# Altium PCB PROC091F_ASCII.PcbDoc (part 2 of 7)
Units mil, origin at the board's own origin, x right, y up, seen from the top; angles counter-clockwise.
Board outline 3590.95 x 906.17 mil, 8 copper layers (Top Layer, GND1, Sig1, PWR1, PWR2, Sig2, GND2, Bottom Layer), stack 63.146 mil thick; 420 components, 316 nets, 1432 pads, 774 vias.
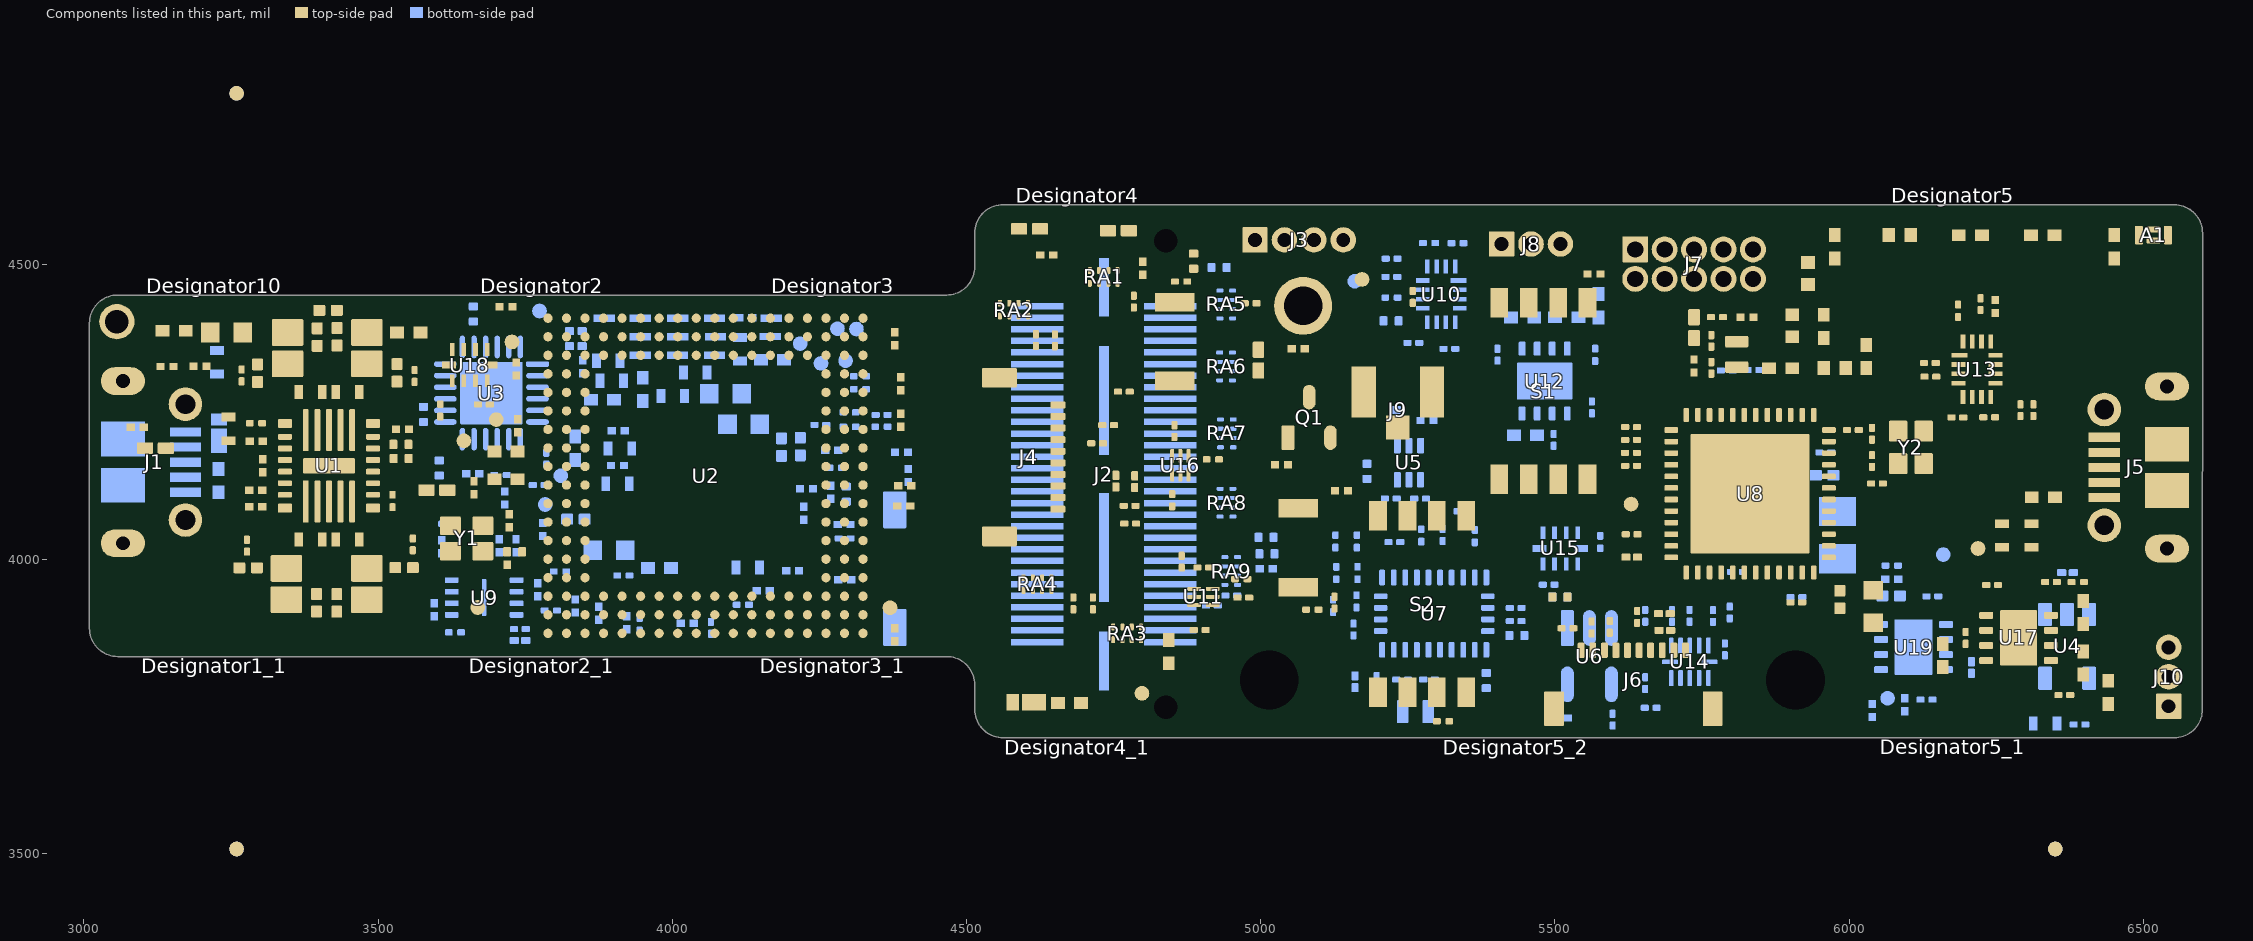
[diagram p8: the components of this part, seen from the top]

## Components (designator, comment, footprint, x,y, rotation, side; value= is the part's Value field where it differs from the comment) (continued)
LD3 "APHHS1005CGCK" APHHS1005_Green 4758.14,4558.15 r0 top
LD4 "APHHS1005CGCK" APHHS1005_Green 3600,4117.07 r0 top
LD5 "APHHS1005CGCK" APHHS1005_Green 4996.12,4338.02 r270 top
LD6 "APHHS1005CGCK" APHHS1005_Green 5736.37,4393.36 r90 top
Q1 "BSS123-7-F" FP-BSS123-7-F_SOT23-IPC_C 5082.37,4240.81 r90 top
R1 "RR0306P-103-D" FP-RR0306P-103-D_0201-IPC_C 5577.06,4028.97 r90 bottom
R2 "RC0201JR-070RL" "FP-RC0201JR-070RL_0201 (0603 Metric)-MFG" 4295.7,4110.3 r270 bottom
R3 "RR0306P-103-D" FP-RR0306P-103-D_0201-IPC_C 3793.63,3912.76 r180 bottom
R4 "CRCW0201100KFKED" 0201L 3717.54,4429.01 r180 top
R5 "CRCW0201100KFKED" 0201L 4378.13,4374.27 r270 top
R6 "CRCW020133R2FNED" 0201L 3706.27,4022.49 r270 bottom
R7 "RR0306P-103-D" FP-RR0306P-103-D_0201-IPC_C 3944.52,3889.21 r90 bottom
R8 "RR0306P-103-D" FP-RR0306P-103-D_0201-IPC_C 3916.9,3972.12 r180 bottom
R9 "CRCW0201100KFKED" 0201L 3835,3920.2 r270 bottom
R10 "AC0201FR-0720RL" FP-AC0201FR-0720RL_0201-IPC_C 4917.01,3921 r180 bottom
R11 "AC0201FR-0720RL" FP-AC0201FR-0720RL_0201-IPC_C 4950.01,3937.94 r180 bottom
R12 "RC0201JR-070RL" "FP-RC0201JR-070RL_0201 (0603 Metric)-MFG" 4929.17,4495.46 r0 bottom
R13 "RC0201JR-07220RL" 0201L 4636.42,4516.76 r180 top locked
R14 "RC0201JR-070RL" "FP-RC0201JR-070RL_0201 (0603 Metric)-MFG" 4886,4506.26 r90 top
R15 "RC0201JR-07220RL" 0201L 3663,4121.49 r90 top
R16 "RC0201FR-077K87L" 0201L 5566.39,4484.46 r180 top
R17 "RC0201JR-07220RL" 0201L 5736.37,4328.17 r90 top
R18 "RR0306P-103-D" FP-RR0306P-103-D_0201-IPC_C 5363.78,4038.98 r270 bottom
R19 "RR0306P-103-D" FP-RR0306P-103-D_0201-IPC_C 3605.65,4252.67 r270 top
R20 "RR0306P-103-D" FP-RR0306P-103-D_0201-IPC_C 6072.37,3988.94 r180 bottom
R21 "RR0306P-103-D" FP-RR0306P-103-D_0201-IPC_C 4318.97,4310.76 r0 bottom
R22 "RR0306P-103-D" FP-RR0306P-103-D_0201-IPC_C 4318.97,4288.76 r0 bottom
R23 "RR0306P-103-D" FP-RR0306P-103-D_0201-IPC_C 4301.24,4249.29 r0 bottom
R24 "CRCW0402200RFKEDHP" FP-CRCW0402200RFKEDHP_0402-IPC_C 6071.37,3937.46 r180 bottom
R25 "RC0201FR-074K99L" 0201L 3292.98,4200.49 r180 top
R26 "RC0201FR-074K99L" 0201L 3292.13,4116.99 r180 top
R27 "RC0201JR-07510RL" 0201L 6094.58,3752.54 r90 bottom
R28 "RC0201JR-070RL" "FP-RC0201JR-070RL_0201 (0603 Metric)-MFG" 3538.8,4195 r180 top
R29 "CRCW0201100KFKED" 0201L 6072.37,3965.94 r180 bottom
R30 "RC0201JR-070RL" "FP-RC0201JR-070RL_0201 (0603 Metric)-MFG" 5221.5,4404.87 r0 bottom locked
R31 "RC0201JR-070RL" "FP-RC0201JR-070RL_0201 (0603 Metric)-MFG" 5010.5,4008.93 r0 bottom
R32 "RC0201JR-070RL" "FP-RC0201JR-070RL_0201 (0603 Metric)-MFG" 3539.13,4171 r180 top
R33 "RC0201FR-074K99L" 0201L 3292.13,4088.65 r180 top
R34 "RC0201FR-074K99L" 0201L 3541.5,4220.5 r0 top
R35 "RR0306P-103-D" FP-RR0306P-103-D_0201-IPC_C 3292.52,4231 r180 top
R36 "RR0306P-103-D" FP-RR0306P-103-D_0201-IPC_C 3524.56,4098.79 r270 top
R37 "CRCW0201100KFKED" 0201L 5009.23,3983.33 r180 bottom
R38 "RC0201FR-074K99L" 0201L 5282.68,4235.46 r0 bottom
R39 "RC0201JR-07510RL" 0201L 3090.67,4224.06 r0 top
R40 "RC0201FR-074K99L" 0201L 3660.79,4145.37 r0 bottom
R41 "RC0201JR-070RL" "FP-RC0201JR-070RL_0201 (0603 Metric)-MFG" 3825.31,4374.62 r90 bottom
R42 "RC0201JR-07220RL" 0201L 4799.25,4494.23 r270 top locked
R43 "RR0306P-103-D" FP-RR0306P-103-D_0201-IPC_C 3630.7,3875.43 r0 bottom
R44 "RR0306P-103-D" FP-RR0306P-103-D_0201-IPC_C 3619.37,4059.85 r0 bottom
R45 "RR0306P-103-D" FP-RR0306P-103-D_0201-IPC_C 3809.22,3978.91 r0 bottom
R46 "CRCW020133R2FNED" 0201L 3595.37,3913.81 r90 bottom
R47 "CRCW020133R2FNED" 0201L 3734.37,4022.49 r270 bottom
R48 "CRCW020133R2FNED" 0201L 3608.37,4021.09 r270 bottom
R49 "CRCW020133R2FNED" 0201L 3771.3,3947.76 r270 bottom
R50 "RC0201JR-071KL" 0201L 3197.4,4327.73 r0 top
R51 "RC0201JR-070RL" "FP-RC0201JR-070RL_0201 (0603 Metric)-MFG" 5230.37,4240.37 r270 bottom locked
R52 "RC0201FR-071K96L" 0201L 3141.4,4327.36 r0 top
R53 "RC0402FR-073R83L" "FP-RC0402FR-073R83L_0402 (1005 Metric)-IPC_C" 3532.13,4316.35 r90 top
R54 "RC0402FR-073R83L" "FP-RC0402FR-073R83L_0402 (1005 Metric)-IPC_C" 3295.13,4316.07 r90 top
R55 "RC0402FR-073R83L" "FP-RC0402FR-073R83L_0402 (1005 Metric)-IPC_C" 3544.13,3985.35 r180 top
R56 "RC0402FR-073R83L" "FP-RC0402FR-073R83L_0402 (1005 Metric)-IPC_C" 3279.13,3985.21 r0 top
R57 "RC0201JR-070RL" "FP-RC0201JR-070RL_0201 (0603 Metric)-MFG" 5180.56,4149.19 r270 bottom locked
R58 "RC0201JR-070RL" "FP-RC0201JR-070RL_0201 (0603 Metric)-MFG" 5008.99,4036.94 r180 bottom
R59 "RR0306P-103-D" FP-RR0306P-103-D_0201-IPC_C 4301.24,4224.76 r0 bottom
R60 "RC0201JR-070RL" "FP-RC0201JR-070RL_0201 (0603 Metric)-MFG" 3846.82,4374.62 r90 bottom
R61 "RC0201JR-070RL" "FP-RC0201JR-070RL_0201 (0603 Metric)-MFG" 3577.24,4245.78 r270 bottom
R62 "RC0201JR-070RL" "FP-RC0201JR-070RL_0201 (0603 Metric)-MFG" 3662,4416.56 r90 bottom
R63 "RC0201JR-070RL" "FP-RC0201JR-070RL_0201 (0603 Metric)-MFG" 3604,4154.79 r270 bottom
R64 "RC0201FR-074K99L" 0201L 3715.38,4103.78 r90 bottom
R65 "RR0306P-103-D" FP-RR0306P-103-D_0201-IPC_C 3708.05,4143.04 r0 bottom
R66 "RC0201JR-070RL" "FP-RC0201JR-070RL_0201 (0603 Metric)-IPC_C" 4982.89,4434.77 r0 top
R67 "RC0201JR-070RL" "FP-RC0201JR-070RL_0201 (0603 Metric)-MFG" 5508.37,3935.46 r0 bottom
R68 "RC0201JR-070RL" "FP-RC0201JR-070RL_0201 (0603 Metric)-MFG" 5508.37,3935.46 r0 top
R69 "RC0201FR-074K99L" 0201L 5511.07,3729.96 r0 bottom
R70 "RC0201JR-070RL" "FP-RC0201JR-070RL_0201 (0603 Metric)-MFG" 5435.37,3870.14 r0 bottom
R71 "RC0201JR-070RL" "FP-RC0201JR-070RL_0201 (0603 Metric)-MFG" 5383.33,3793.46 r270 bottom
R72 "RC0201JR-070RL" "FP-RC0201JR-070RL_0201 (0603 METRIC)-IPC_C" 5433.38,3894.46 r180 bottom
R73 "RC0201JR-070RL" "FP-RC0201JR-070RL_0201 (0603 METRIC)-IPC_C" 5433.37,3917.06 r180 bottom
R74 "RC0201JR-070RL" "FP-RC0201JR-070RL_0201 (0603 METRIC)-IPC_C" 4896.36,3879.46 r0 top locked
R75 "RC0201JR-071KL" 0201L 3875.37,3907.8 r270 bottom
R76 "RC0201JR-070RL" "FP-RC0201JR-070RL_0201 (0603 METRIC)-IPC_C" 5698.97,3903.45 r90 bottom
R77 "RR0306P-103-D" FP-RR0306P-103-D_0201-IPC_C 5163.43,4030.06 r270 bottom locked
R78 "RR0306P-103-D" FP-RR0306P-103-D_0201-IPC_C 5164.52,3976.35 r270 bottom locked
R79 "ERJ-1GNF4701C" FP-ERJ-1GNF4701C_0201-IPC_C 5788.67,3846.46 r90 bottom
R80 "RR0306P-103-D" FP-RR0306P-103-D_0201-IPC_C 5123,3920.48 r90 bottom
R81 "RR0306P-103-D" FP-RR0306P-103-D_0201-IPC_C 5344.92,4081.19 r180 bottom locked
R82 "RR0306P-103-D" FP-RR0306P-103-D_0201-IPC_C 5272.85,4040.2 r270 bottom
R83 "RR0306P-103-D" FP-RR0306P-103-D_0201-IPC_C 4277.8,4155.3 r180 bottom
R84 "RR0306P-103-D" FP-RR0306P-103-D_0201-IPC_C 4119.89,3922.4 r0 bottom
R85 "RR0306P-103-D" FP-RR0306P-103-D_0201-IPC_C 4355.44,4224.99 r0 bottom
R86 "RC0201JR-070RL" "FP-RC0201JR-070RL_0201 (0603 METRIC)-IPC_C" 5629.22,4180.57 r0 top
R87 "RC0201JR-070RL" "FP-RC0201JR-070RL_0201 (0603 METRIC)-IPC_C" 5629.37,4202.46 r0 top
R88 "AC0201FR-0720RL" FP-AC0201FR-0720RL_0201-IPC_C 4778.18,4060.33 r180 top locked
R89 "CRCW0201100KFKED" 0201L 5826.38,4411.08 r0 top
R90 "RC0201JR-070RL" "FP-RC0201JR-070RL_0201 (0603 METRIC)-IPC_C" 5837.39,4321.29 r180 bottom
R91 "RC0201JR-070RL" "FP-RC0201JR-070RL_0201 (0603 METRIC)-IPC_C" 5910.14,3926.46 r180 top
R92 "CRCW0201100KFKED" 0201L 6039.37,3742.65 r270 bottom
R93 "RR0306P-103-D" FP-RR0306P-103-D_0201-IPC_C 5126.93,4030.08 r90 bottom locked
R94 "RR0306P-103-D" FP-RR0306P-103-D_0201-IPC_C 5286.18,4537.08 r0 bottom locked
R95 "RR0306P-103-D" FP-RR0306P-103-D_0201-IPC_C 5222.16,4444.39 r180 bottom locked
R96 "RR0306P-103-D" FP-RR0306P-103-D_0201-IPC_C 5162.8,3928.09 r90 bottom locked
R97 "RC0201JR-070RL" "FP-RC0201JR-070RL_0201 (0603 METRIC)-IPC_C" 5309.27,4040.92 r90 bottom
R98 "RR0306P-103-D" FP-RR0306P-103-D_0201-IPC_C 5128.47,3976.25 r90 bottom locked
R99 "RC0201JR-070RL" "FP-RC0201JR-070RL_0201 (0603 METRIC)-IPC_C" 5222.1,4479.52 r180 bottom locked
R100 "RC0201JR-070RL" "FP-RC0201JR-070RL_0201 (0603 METRIC)-IPC_C" 5320.66,4357.38 r0 bottom
R101 "RC0201JR-070RL" "FP-RC0201JR-070RL_0201 (0603 METRIC)-IPC_C" 5222.36,4510.46 r180 bottom
R102 "RC0201JR-070RL" "FP-RC0201JR-070RL_0201 (0603 METRIC)-IPC_C" 5792.03,4320.41 r0 bottom
R103 "RC0201JR-070RL" "FP-RC0201JR-070RL_0201 (0603 METRIC)-IPC_C" 4355.64,4245.1 r0 bottom
R104 "RR0306P-103-D" FP-RR0306P-103-D_0201-IPC_C 4966.89,3965.95 r0 top locked
R105 "RC0201JR-070RL" "FP-RC0201JR-070RL_0201 (0603 METRIC)-IPC_C" 4865.78,3995.57 r90 top
R106 "RC0201JR-070RL" "FP-RC0201JR-070RL_0201 (0603 METRIC)-IPC_C" 4902.35,3985.56 r0 top locked
R107 "RC0201JR-07510RL" 0201L 5063.61,4357.18 r180 top
R108 "RC0201JR-07510RL" 0201L 5035.32,4159.98 r0 top
R109 "RC0201JR-070RL" "FP-RC0201JR-070RL_0201 (0603 Metric)-MFG" 3732.14,4012.38 r0 top
R110 "RR0306P-103-D" FP-RR0306P-103-D_0201-IPC_C 5309.89,3724.46 r0 top
R111 "RC0201JR-07220RL" 0201L 5137.39,4116.46 r0 top
R112 "RC0201JR-070RL" "FP-RC0201JR-070RL_0201 (0603 METRIC)-IPC_C" 5259.36,4367.46 r0 bottom
R113 "RC0201JR-070RL" "FP-RC0201JR-070RL_0201 (0603 METRIC)-IPC_C" 5258.37,4445.48 r270 top
R114 "CRCW040261R9FKED" 0402L 6397.76,3909.29 r270 top
R115 "RC0201JR-070RL" "FP-RC0201JR-070RL_0201 (0603 Metric)-IPC_C" 6342.98,3961 r0 top
R116 "RC0201JR-070RL" "FP-RC0201JR-070RL_0201 (0603 Metric)-IPC_C" 6242.98,3956 r0 top
R117 "CRCW040261R9FKED" 0402L 6397.85,3823.52 r270 top
R118 "RR0306P-103-D" FP-RR0306P-103-D_0201-IPC_C 6185,4422 r90 top
R119 "CRCW040261R9FKED" 0402L 5520.06,4410.82 r180 bottom
R120 "RC0201JR-070RL" "FP-RC0201JR-070RL_0201 (0603 Metric)-IPC_C" 6291,4252.99 r90 top
R121 "RC0201JR-070RL" "FP-RC0201JR-070RL_0201 (0603 METRIC)-IPC_C" 6137.23,4333.23 r180 top
R122 "RR0306P-103-D" FP-RR0306P-103-D_0201-IPC_C 5568.37,4347.11 r270 bottom
R123 "RC0201JR-070RL" "FP-RC0201JR-070RL_0201 (0603 METRIC)-IPC_C" 5562.87,4257.76 r90 bottom
R124 "RR0306P-103-D" FP-RR0306P-103-D_0201-IPC_C 4864.68,4471.7 r0 top
R125 "RR0306P-103-D" FP-RR0306P-103-D_0201-IPC_C 5087.65,3914.04 r0 top
R126 "CRCW040261R9FKED" 0402L 5445.1,4410.54 r180 bottom
R127 "RC0201JR-070RL" "FP-RC0201JR-070RL_0201 (0603 METRIC)-IPC_C" 6137.99,4310 r0 top
R128 "RC0201JR-070RL" "FP-RC0201JR-070RL_0201 (0603 METRIC)-IPC_C" 6183.91,4240.71 r180 top
R129 "RC0201JR-070RL" "FP-RC0201JR-070RL_0201 (0603 METRIC)-IPC_C" 5125.2,3925.93 r90 top
R130 "AC0201FR-0720RL" FP-AC0201FR-0720RL_0201-IPC_C 4617.95,4372.15 r270 top locked
R131 "RC0201JR-070RL" "FP-RC0201JR-070RL_0201 (0603 METRIC)-IPC_C" 5809.36,3978.41 r180 bottom
R132 "AC0201FR-0720RL" FP-AC0201FR-0720RL_0201-IPC_C 4777.33,4090.57 r180 top locked
R133 "AC0201FR-0720RL" FP-AC0201FR-0720RL_0201-IPC_C 4740.67,4227.63 r180 top locked
R134 "RR0306P-103-D" FP-RR0306P-103-D_0201-IPC_C 6388.49,3961 r0 top
R135 "AC0201FR-0720RL" FP-AC0201FR-0720RL_0201-IPC_C 4722.06,4196.8 r180 top locked
R136 "RC0201JR-070RL" "FP-RC0201JR-070RL_0201 (0603 Metric)-IPC_C" 6238.01,4241 r0 top
R137 "AC0201FR-0720RL" FP-AC0201FR-0720RL_0201-IPC_C 4681.54,3924.7 r90 top locked
R138 "AC0201FR-0720RL" FP-AC0201FR-0720RL_0201-IPC_C 4767.38,4284.46 r180 top
R139 "RC0201JR-070RL" "FP-RC0201JR-070RL_0201 (0603 Metric)-IPC_C" 6313,4252.99 r270 top
R140 "AC0201FR-0720RL" FP-AC0201FR-0720RL_0201-IPC_C 4714.81,3924.69 r90 top locked
R141 "RC0201FR-074K99L" 0201L 6248.22,4429.26 r90 top
R158 "RC0201FR-0782K5L" 0201L 4228.2,4119.6 r0 bottom
R159 "RC0201JR-07750RL" 0201L 4223.5,4078.1 r270 bottom
R160 "RC0201JR-070RL" "FP-RC0201JR-070RL_0201 (0603 METRIC)-IPC_C" 5768.53,3903.27 r90 bottom
R161 "RC0201JR-070RL" "FP-RC0201JR-070RL_0201 (0603 METRIC)-IPC_C" 5629.37,4158.46 r0 top
R166 "RC0201JR-070RL" "FP-RC0201JR-070RL_0201 (0603 METRIC)-IPC_C" 5728.8,3903.59 r90 bottom
R168 "RC0201JR-070RL" "FP-RC0201JR-070RL_0201 (0603 METRIC)-IPC_C" 5653.43,3903.57 r90 bottom
R170 "RC0201FR-0782K5L" 0201L 4154.35,3946.46 r180 bottom
R171 "RC0201JR-07750RL" 0201L 4204.44,3980.18 r0 bottom
R172 "RC0201FR-0782K5L" 0201L 4401.11,4142.03 r90 bottom
R174 "RC0201FR-077K87L" 0201L 4269.1,4113.8 r90 bottom
R176 "RC0201FR-077K87L" 0201L 4389.6,4181.8 r0 bottom
R177 "RR0306P-103-D" FP-RR0306P-103-D_0201-IPC_C 4849.59,4099.95 r90 top
R178 "RR0306P-103-D" FP-RR0306P-103-D_0201-IPC_C 4918.69,4169.46 r180 top
R180 "ERJ-1GNF4701C" FP-ERJ-1GNF4701C_0201-IPC_C 5653.37,3789.15 r270 bottom
R181 "ERJ-1GNF4701C" FP-ERJ-1GNF4701C_0201-IPC_C 5639.79,3901.65 r90 top
R182 "RC0201JR-070RL" "FP-RC0201JR-070RL_0201 (0603 METRIC)-IPC_C" 4650.14,4371.83 r270 top locked
R183 "RC0201JR-070RL" "FP-RC0201JR-070RL_0201 (0603 METRIC)-IPC_C" 5593.19,3884.84 r90 top
R184 "RC0201JR-070RL" "FP-RC0201JR-070RL_0201 (0603 METRIC)-IPC_C" 5562.38,3883.78 r90 top
R185 "RC0201JR-070RL" "FP-RC0201JR-070RL_0201 (0603 METRIC)-IPC_C" 5521.36,3882.46 r180 top
RA1 "EXB-18VR000X" FP-EXB-18VR000X_0502-MFG 4733.17,4479.49 r180 top locked
RA2 "EXB-18VR000X" FP-EXB-18VR000X_0502-MFG 4580.6,4423.99 r180 top locked
RA3 "EXB-18VR000X" FP-EXB-18VR000X_0502-MFG 4772.94,3873.84 r0 top locked
RA4 "EXB-18VR000X" FP-EXB-18VR000X_0502-MFG 4620.57,3957.49 r0 top locked
RA5 "EXB-18VR000X" FP-EXB-18VR000X_0502-MFG 4941.51,4432.71 r90 bottom locked
RA6 "EXB-18VR000X" FP-EXB-18VR000X_0502-MFG 4941.09,4327.39 r90 bottom locked
RA7 "EXB-18VR000X" FP-EXB-18VR000X_0502-MFG 4942.52,4213.65 r90 bottom locked
RA8 "EXB-18VR000X" FP-EXB-18VR000X_0502-MFG 4941.86,4095.87 r90 bottom locked
RA9 "EXB-18VR000X" FP-EXB-18VR000X_0502-MFG 4949.85,3979.76 r90 bottom locked
S1 "218-4LPST" SW_218-4LPST 5480.37,4285.46 r90 top
S2 "218-4LPST" SW_218-4LPST 5274.37,3923.46 r90 top
S3 "CHS-01TA" FP-CHS-01TA_SMT_SW_5MM4_2MM5-MFG 4378.13,3983.7 r270 bottom
SW2 "B3U-1000P" SW_B3U-1000P 4854.16,4369.94 r270 top
SW3 "B3U-1000P" SW_B3U-1000P 5063.87,4019.39 r90 top
TP2 "TESTPOINT" TP_25MIL-SMT 3810.59,4141.77 r90 bottom
TP3 "TESTPOINT" TP_25MIL-SMT 3784,4092.76 r90 bottom
TP4 "TESTPOINT" TP_25MIL-SMT 6159.89,4007.65 r180 bottom
TP5 "TESTPOINT" TP_25MIL-SMT 3669.3,3917.72 r90 top
TP6 "TESTPOINT" TP_25MIL-SMT 4313,4390.94 r0 bottom
TP7 "TESTPOINT" TP_25MIL-SMT 4280.69,4391.59 r270 bottom
TP8 "TESTPOINT" TP_25MIL-SMT 4252.7,4332.6 r90 bottom
TP9 "TESTPOINT" TP_25MIL-SMT 4217.3,4366.19 r90 bottom
TP10 "TESTPOINT" TP_25MIL-SMT 6065.37,3763.46 r270 bottom
TP11 "TESTPOINT" TP_25MIL-SMT 4370,3917.37 r90 top
TP12 "TESTPOINT" TP_VIA_060RND040 3056.09,4403.54 r90 top
TP13 "TESTPOINT" TP_25MIL-SMT 4798.18,3771.83 r270 top
TP14 "TESTPOINT" TP_25MIL-SMT 4294.6,4337.1 r180 bottom
TP15 "TESTPOINT" TP_25MIL-SMT 6219,4018 r90 top
TP16 "TESTPOINT" TP_25MIL-SMT 5629.37,4093.46 r180 top
TP17 "TESTPOINT" TP_25MIL-SMT 3701,4237 r270 top
TP18 "TESTPOINT" TP_25MIL-SMT 3727.56,4369.01 r90 top
TP19 "TESTPOINT" TP_25MIL-SMT 3645.95,4200.94 r90 top
TP20 "4953" FP-4953_HDR1-MFG 5072.16,4430.47 r180 bottom locked
TP26 "TESTPOINT" TP_25MIL-SMT 3774.42,4421.63 r0 bottom
TP27 "TESTPOINT" TP_25MIL-SMT 5172.19,4475.26 r270 top
TP46 "TESTPOINT" TP_25MIL-SMT 5159.8,4472.11 r180 bottom locked
U1 "LP87524JRNFRQ1" RNF0026C 3416.61,4158.52 r180 top
U2 "XI6843ARQGALP" ALP0180A 4056.48,4141.61 r90 top
U3 "CP2105-F01-GMR" FP-CP2105-F01-GMR_QFN24-EP-IPC_A 3692.64,4282.2 r180 bottom
U4 "TPS79330DBVR" DBV0005A_N 6370.37,3851.63 r270 bottom
U5 "TMP112AQDRLRQ1" DRL0006A 5251.98,4163.77 r270 bottom locked
U6 "CAT24C08TDI-GT3" FP-CAT24C08TDI-GT3_TSOT-23-5-IPC_A 5558.54,3835.01 r270 bottom
U7 "BNO085" FP-BNO085_LGA28-MFG 5294.88,3907.22 r270 bottom
U8 "CC2642R1FRGZR" RGZ0048A 5831.57,4111.11 r270 top
U9 "MX25R1635FZUIH0" USON-8L 3680.29,3934.68 r0 bottom
U10 "TCA6408ARSVR" RSV0016A 5306.8,4449.73 r180 bottom locked
U11 "SN74LVC1G3157DSFR" DSF0006A 4902.7,3935.72 r0 top locked
U12 "TCAN1042HGVDRBRQ1" DRB0008F#1 5482.58,4302.51 r90 bottom
U13 "TS3A5018RSVR" RSV0016A 6217.13,4322.76 r0 top
U14 "TXB0104QRUTRQ1" RUT0012A 5729.23,3825.36 r90 bottom
U15 "TS5A23157RSER" RSE0010A 5509.21,4018.34 r270 bottom
U16 "SN74LVC1G11DSFR" DSF0006A-MFG 4863.37,4159.46 r90 top
U17 "TCAN1042HGVDRBRQ1" DRB0008F#2 6287.97,3866 r0 top
U18 "TS5A23157RSER" RSE0010A 3655.79,4329.59 r270 top
U19 "TPS2115ADRBR" DRB0008B 6109.37,3850.46 r0 bottom
Y1 "CX2016DB40000D0FLJCC" FP-CX2016DB40000D0FLJCC_SMT_2MM0_1MM6-MFG 3650.54,4035.03 r0 top
Y2 "CX2016DB48000C0WPLA2" FP-CX2016DB48000C0WPLA2_SMD4-MFG 6104.9,4189.85 r270 top
Y3 "ABS05W-32.768KHZ-D-2-T" FP-ABS05W-32.768KHZ-D-2-T_XTAL_SMT_1MM6_1MM0-MFG 5808.9,4347.93 r270 top
Y4 "ABS05W-32.768KHZ-D-2-T" FP-ABS05W-32.768KHZ-D-2-T_XTAL_SMT_1MM6_1MM0-MFG 5262.82,3740.88 r0 bottom locked
ZZ1 "This Assembly Note is for PCB labels only" AssemblyNoteLabel 2349.62,2814.36 r0 top
ZZ2 "These assemblies are ESD sensitive, ESD precautions shall be observed." AssemblyNote 2346.49,2738.89 r0 top
ZZ3 "These assemblies must be clean and free from flux and all contaminants. Use of no clean flux is not acceptable." AssemblyNote 2346.43,2653.5 r0 top
ZZ4 "These assemblies must comply with workmanship standards IPC-A-610 Class 2, unless otherwise specified." AssemblyNote 2343.34,2567.2 r0 top
ZZ5.1 "Cut the thermal pad(Part Number#GPVOUS-0.125-AC-0816) for the shape and size of the inner surface of the heatsink(Part Number#MCH054) and paste it on the inner surface of the heatsink;" AssemblyNote 2340.76,2492.7 r0 top
ZZ5.2 "Bring the heatsink onto the PCB bottom side (Opposite side of AOP device). Match the teeth in the heatsink with break-away area in the PCB and press the heatsink onto the PCB slightly so as thermal pad is spread all over the area" AssemblyNote 2343.41,2409 r0 top

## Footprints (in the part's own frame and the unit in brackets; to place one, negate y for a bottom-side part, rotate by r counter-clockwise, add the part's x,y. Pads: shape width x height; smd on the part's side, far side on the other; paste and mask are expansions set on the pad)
0201_033L [mm] "0201"
  rect 0.36x0.32 smd mask+0: 1(-0.28,0) 2(0.28,0)
0201L [mm] "Data from Kemet datasheet CC101_COM dated 7/28/11"
  rect 0.36x0.32 smd mask+0: 1(-0.28,0) 2(0.28,0)
0402_070 [mil] "SMD, 2-Leads, Body 1.2x0.7mm, Height 0.7mm"
  rect 15x24 smd: 1(-20,0) 2(20,0)
0402L [mm] "0402 from SM-752 data"
  rect 0.6x0.5 smd: 1(-0.5,0) 2(0.5,0)
0603L [mm] "0603 from SM-752 data"
  rect 0.8x0.85 smd: 1(-0.7,0) 2(0.7,0)
  silkscreen extent -0.07,-0.33 0.07,0.33
0805_HV [mil] "0805 with 30mil clearance between pads"
  rect 50x63 smd: 1(-40,0) 2(40,0)
  silkscreen extent -74,-40 74,40
ALP0180A [mm] "BGA-180"
  round 0.4 smd: A1(-6.8,6.8) A2(-6,6.8) A3(-5.2,6.8) A4(-4.4,6.8) A5(-3.6,6.8) A6(-2.8,6.8) A7(-2,6.8) A8(-1.2,6.8) A9(-0.4,6.8) A10(0.4,6.8) A11(1.2,6.8) A12(2,6.8) A13(2.8,6.8) A14(3.6,6.8) A15(4.4,6.8) A16(5.2,6.8) A17(6,6.8) A18(6.8,6.8) B1(-6.8,6) B2(-6,6) B3(-5.2,6) B4(-4.4,6) B5(-3.6,6) B6(-2.8,6) B7(-2,6) B8(-1.2,6) B9(-0.4,6) B10(0.4,6) B11(1.2,6) B12(2,6) B13(2.8,6) B14(3.6,6) B15(4.4,6) B16(5.2,6) B17(6,6) B18(6.8,6) C1(-6.8,5.2) C2(-6,5.2) C3(-5.2,5.2) C4(-4.4,5.2) C5(-3.6,5.2) C6(-2.8,5.2) C7(-2,5.2) C8(-1.2,5.2) C9(-0.4,5.2) C10(0.4,5.2) C11(1.2,5.2) C12(2,5.2) C13(2.8,5.2) C14(3.6,5.2) C15(4.4,5.2) C16(5.2,5.2) C17(6,5.2) C18(6.8,5.2) D1(-6.8,4.4) D2(-6,4.4) D3(-5.2,4.4) D16(5.2,4.4) D17(6,4.4) D18(6.8,4.4) E1(-6.8,3.6) E2(-6,3.6) E3(-5.2,3.6) E16(5.2,3.6) E17(6,3.6) E18(6.8,3.6) F1(-6.8,2.8) F2(-6,2.8) F3(-5.2,2.8) F16(5.2,2.8) F17(6,2.8) F18(6.8,2.8) G1(-6.8,2) G2(-6,2) G3(-5.2,2) G16(5.2,2) G17(6,2) G18(6.8,2) H1(-6.8,1.2) H2(-6,1.2) H3(-5.2,1.2) H16(5.2,1.2) H17(6,1.2) H18(6.8,1.2) J1(-6.8,0.4) J2(-6,0.4) J3(-5.2,0.4) J16(5.2,0.4) J17(6,0.4) J18(6.8,0.4) K1(-6.8,-0.4) K2(-6,-0.4) K3(-5.2,-0.4) K16(5.2,-0.4) K17(6,-0.4) K18(6.8,-0.4) L1(-6.8,-1.2) L2(-6,-1.2) L3(-5.2,-1.2) L16(5.2,-1.2) L17(6,-1.2) L18(6.8,-1.2) M1(-6.8,-2) M2(-6,-2) M3(-5.2,-2) M16(5.2,-2) M17(6,-2) M18(6.8,-2) N1(-6.8,-2.8) N2(-6,-2.8) N3(-5.2,-2.8) N16(5.2,-2.8) N17(6,-2.8) N18(6.8,-2.8) P1(-6.8,-3.6) P2(-6,-3.6) P3(-5.2,-3.6) P16(5.2,-3.6) P17(6,-3.6) P18(6.8,-3.6) R1(-6.8,-4.4) R2(-6,-4.4) R3(-5.2,-4.4) R16(5.2,-4.4) R17(6,-4.4) R18(6.8,-4.4) T1(-6.8,-5.2) T2(-6,-5.2) T3(-5.2,-5.2) T4(-4.4,-5.2) T5(-3.6,-5.2) T6(-2.8,-5.2) T7(-2,-5.2) T8(-1.2,-5.2) T9(-0.4,-5.2) T10(0.4,-5.2) T11(1.2,-5.2) T12(2,-5.2) T13(2.8,-5.2) T14(3.6,-5.2) T15(4.4,-5.2) T16(5.2,-5.2) T17(6,-5.2) T18(6.8,-5.2) U1(-6.8,-6) U2(-6,-6) U3(-5.2,-6) U4(-4.4,-6) U5(-3.6,-6) U6(-2.8,-6) U7(-2,-6) U8(-1.2,-6) U9(-0.4,-6) U10(0.4,-6) U11(1.2,-6) U12(2,-6) U13(2.8,-6) U14(3.6,-6) U15(4.4,-6) U16(5.2,-6) U17(6,-6) U18(6.8,-6) V1(-6.8,-6.8) V2(-6,-6.8) V3(-5.2,-6.8) V4(-4.4,-6.8) V5(-3.6,-6.8) V6(-2.8,-6.8) V7(-2,-6.8) V8(-1.2,-6.8) V9(-0.4,-6.8) V10(0.4,-6.8) V11(1.2,-6.8) V12(2,-6.8) V13(2.8,-6.8) V14(3.6,-6.8) V15(4.4,-6.8) V16(5.2,-6.8) V17(6,-6.8) V18(6.8,-6.8)
  silkscreen extent -7.5,-7.5 7.5,7.5
APHHS1005_Green [mm] "SMD, 2-Leads, Body 1x0.5mm"
  rrect20% 0.7x0.5 smd: 1(-0.45,0) 2(0.45,0)
  silkscreen extent -0.8,-0.65 1.2,0.65
AssemblyNote [mil] "Assembly Note"
AssemblyNoteLabel [mil] "Assembly Note for PCB Labels"
BRAKE_WAY_HOLES1X2 [mil]
  round 27 hole 32 unplated mask+0: ""(-50,30.26) ""(0,30.26) ""(50,30.26)
CONN_105017-0001 [mm] "Molex Micro USB-B"
  rect 0.4x1.35 smd: 1(-1.3,1.35) 2(-0.65,1.35) 3(0,1.35) 4(0.65,1.35) 5(1.3,1.35)
  oval 1.2x1.9 hole 0.6 slot 1.3 at 90 deg: 6(-3.5,-1.35) 9(3.5,-1.35)
  rect 1.5x1.9 smd: 7(-1,-1.35) 8(1,-1.35)
  round 1.45 hole 0.85: 10(2.5,1.35) 11(-2.5,1.35)
  Top Layer region: -3.5,-0.4 -2.3,-0.4 -2.3,-2.3 -3.5,-2.3
  Top Layer region: 3.5,-2.3 2.3,-2.3 2.3,-0.4 3.5,-0.4
  silkscreen extent -4.1,-0.2 4.1,1.4
CONN_UFL-R-SMT-1 [mm] "Hirose recommended land pattern http://www.hirose.co.jp/cataloge_hp/e32119372.pdf 2009.2"
  rect 1.05x1 smd paste-0.1 mask+0: 1(-1.525,0)
  rect 2x0.9 on Top Paste: 2(0,1.5) 3(0,-1.5)
  rect 2x0.9 on Top Solder: 2(0,1.5) 3(0,-1.5)
  rect 2.2x1.05 smd paste-2 mask+0: 2(0,1.475) 3(0,-1.475)
  Top Layer keep-out region: -0.8,-0.702 1.1,-0.702 1.1,0.698 -0.8,0.698
  silkscreen extent -1.7,-1.7 1.7,1.7
DBV0005A_N [mm] "SOT23, 5-Leads, Body 2.9x1.6mm, Pitch 0.95mm, Lead Span 2.8mm, IPC Medium Density"
  rrect17% 1x0.6 smd: 1(-1.375,0.95) 2(-1.375,0) 3(-1.375,-0.95) 4(1.375,-0.95) 5(1.375,0.95)
  silkscreen extent -0.25,-1.55 0.25,1.55
DRB0008B [mm] "SON, 8-Leads, Body 3x3mm, Pitch 0.65mm, Thermal Pad 2.4x1.65mm, TI Recommended"
  rrect33% 0.6x0.3 smd: 1(-1.4,0.975) 2(-1.4,0.325) 3(-1.4,-0.325) 4(-1.4,-0.975) 5(1.4,-0.975) 6(1.4,-0.325) 7(1.4,0.325) 8(1.4,0.975)
  rrect9% 1.47x1.06 on Bottom Paste: 9(0,-0.63) 9(0,0.63)
  rrect6% 1.65x2.4 smd paste-1.2: 9(0,0)
  silkscreen extent -1.73,-1.73 1.73,1.73
DRB0008F#1 [mm] "SON, 8-Leads, Body 3x3mm, Pitch 0.65mm, Thermal Pad 2.4x1.6mm, TI Recommended"
  rrect33% 0.6x0.3 smd: 1(-1.4,0.975) 2(-1.4,0.325) 3(-1.4,-0.325) 4(-1.4,-0.975) 5(1.4,-0.975) 6(1.4,-0.325) 7(1.4,0.325) 8(1.4,0.975)
  rrect9% 1.47x1.07 on Bottom Paste: 9(0,-0.635) 9(0,0.635)
  rrect6% 1.6x2.4 smd paste-1.2: 9(0,0)
  silkscreen extent -1.73,-1.73 1.73,1.73
DRB0008F#2 [mm] "SON, 8-Leads, Body 3x3mm, Pitch 0.65mm, Thermal Pad 2.4x1.6mm, TI Recommended"
  rrect33% 0.6x0.3 smd: 1(-1.4,0.975) 2(-1.4,0.325) 3(-1.4,-0.325) 4(-1.4,-0.975) 5(1.4,-0.975) 6(1.4,-0.325) 7(1.4,0.325) 8(1.4,0.975)
  rrect9% 1.47x1.07 on Top Paste: 9(0,-0.635) 9(0,0.635)
  rrect6% 1.6x2.4 smd paste-1.2: 9(0,0)
  silkscreen extent -1.73,-1.73 1.73,1.73
DRL0006A [mm] "SOTFL, 6-Flat Leads, Body 1.2x1.6x0.6mm, Pitch 0.5mm, TI recommended"
  rrect33% 0.67x0.3 smd: 1(-0.74,0.5) 2(-0.74,0) 3(-0.74,-0.5) 4(0.74,-0.5) 5(0.74,0) 6(0.74,0.5)
  silkscreen extent -0.9,-0.95 0.5,0.95
DSF0006A [mm] "TI recommended land pattern"
  rrect59% 0.6x0.17 smd mask+0: 1(-0.4,0.35) 2(-0.4,0) 3(-0.4,-0.35) 4(0.4,-0.35) 5(0.4,0) 6(0.4,0.35)
  silkscreen extent -0.6,-0.63 0.6,0.63
DSF0006A-MFG [mm]
  rrect59% 0.6x0.17 smd paste+0 mask+0: 1(-0.4,0.35) 2(-0.4,0) 3(-0.4,-0.35) 4(0.4,-0.35) 5(0.4,0) 6(0.4,0.35)
  silkscreen extent -1.14,-0.85 0.53,1.02
DSN2_0603 [mm] "SMD, 2-Leads, Body 1.6x0.8mm"
  rect 0.52x0.7 smd: 1(-0.64,0)
  rect 1.05x0.7 smd: 2(0.275,0)
  silkscreen extent -1.4,-0.75 0.8,0.65
FIDUCIAL6.4-20 [mil]
  round 25 smd mask+0: 1(0,0)
FP-250R05L120JV4T_0201-IPC_C [mm]
  rrect38% 0.363x0.263 smd paste+0 mask+0: 1(-0.25,0) 2(0.25,0)
FP-4953_HDR1-MFG [mm]
  round 2.5 hole 1.65 paste-1000 mask+0: 1(0,0)
FP-51441-1093_CONN_SMD_FFC-0 [mm]
  rrect33% 0.3x0.65 smd paste+0 mask+0: 1(-2.25,1.775) 2(-1.75,1.775) 3(-1.25,1.775) 4(-0.75,1.775) 5(-0.25,1.775) 6(0.25,1.775) 7(0.75,1.775) 8(1.25,1.775) 9(1.75,1.775) 10(2.25,1.775)
  rrect12% 0.85x1.5 smd paste+0 mask+0: 11(-3.425,-0.75) 12(3.425,-0.75)
FP-ABS05W-32.768KHZ-D-2-T_XTAL_SMT_1MM6_1MM0-MFG [mm]
  rrect20% 0.5x1 smd paste+0 mask+0: 1(-0.55,0) 2(0.55,0)
FP-AC0201FR-0720RL_0201-IPC_C [mil]
  rrect38% 13.94x10.34 smd paste+0 mask+0: 1(-10.01,0) 2(10.01,0)
FP-ANT016008LCS2442MA2_SMT_ANT-0 [mm]
  rrect29% 0.35x0.8 smd paste+0 mask+0: 1(-0.625,0) 4(0.625,0)
  rrect38% 0.6x0.26 smd paste+0 mask+0: 2-3(0,-0.235) 5-6(0,0.235)
FP-BNO085_LGA28-MFG [mm]
  rrect40% 0.675x0.25 smd paste+0 mask+0: 1(1.562,2.25) 6(-1.562,2.25) 7(-1.562,1.75) 8(-1.562,1.25) 9(-1.562,0.75) 10(-1.562,0.25) 11(-1.562,-0.25) 12(-1.562,-0.75) 13(-1.562,-1.25) 14(-1.562,-1.75) 15(-1.562,-2.25) 20(1.562,-2.25) 21(1.562,-1.75) 22(1.562,-1.25) 23(1.562,-0.75) 24(1.562,-0.25) 25(1.562,0.25) 26(1.562,0.75) 27(1.562,1.25) 28(1.562,1.75)
  rrect40% 0.25x0.575 smd paste+0 mask+0: 2(0.75,2.312) 3(0.25,2.312) 4(-0.25,2.312) 5(-0.75,2.312) 16(-0.75,-2.312) 17(-0.25,-2.312) 18(0.25,-2.312) 19(0.75,-2.312)
FP-BSS123-7-F_SOT23-IPC_C [mm]
  rrect18% 1.059x0.547 smd paste+0 mask+0: 1(-0.877,0.915)
  rrect100% 1.059x0.547 smd paste+0 mask+0: 2(-0.877,-0.915) 3(0.877,0)
FP-CAT24C08TDI-GT3_TSOT-23-5-IPC_A [mm]
  rrect18% 1.54x0.566 smd paste+0 mask+0: 1(-1.216,0.95)
  rrect100% 1.54x0.566 smd paste+0 mask+0: 2(-1.216,0) 3(-1.216,-0.95) 4(1.216,-0.95) 5(1.216,0.95)
FP-CHS-01TA_SMT_SW_5MM4_2MM5-MFG [mm]
  rrect10% 1.6x1 smd paste+0 mask+0: 1(-2.54,0) 2(2.54,0)
FP-CL03A103KA3NNNC_0201-IPC_C [mil]
  rrect38% 13.94x10.34 smd paste+0 mask+0: 1(-10.01,0) 2(10.01,0)
FP-CL03A105MO3NRNH_0201-IPC_C [mil]
  rrect33% 15.83x11.94 smd paste+0 mask+0: 1(-9.87,0) 2(9.87,0)
FP-CL05A226MQ5N6J8_0402-IPC_C [mil]
  rrect21% 20.29x18.6 smd paste+0 mask+0: 1(-14.9,0) 2(14.9,0)
FP-CP2105-F01-GMR_QFN24-EP-IPC_A [mm]
  rrect42% 0.979x0.239 smd paste+0 mask+0: 1(-1.99,1.25)
  rrect100% 0.979x0.239 smd paste+0 mask+0: 2(-1.99,0.75) 3(-1.99,0.25) 4(-1.99,-0.25) 5(-1.99,-0.75) 6(-1.99,-1.25) 13(1.99,-1.25) 14(1.99,-0.75) 15(1.99,-0.25) 16(1.99,0.25) 17(1.99,0.75) 18(1.99,1.25)
  rrect100% 0.239x0.979 smd paste+0 mask+0: 7(-1.25,-1.99) 8(-0.75,-1.99) 9(-0.25,-1.99) 10(0.25,-1.99) 11(0.75,-1.99) 12(1.25,-1.99) 19(1.25,1.99) 20(0.75,1.99) 21(0.25,1.99) 22(-0.25,1.99) 23(-0.75,1.99) 24(-1.25,1.99)
  rrect4% 2.7x2.7 smd paste-1000 mask+0: 25(0,0)
FP-CRCW0402200RFKEDHP_0402-IPC_C [mil]
  rrect21% 20.29x18.6 smd paste+0 mask+0: 1(-14.9,0) 2(14.9,0)
FP-CX2016DB40000D0FLJCC_SMT_2MM0_1MM6-MFG [mm]
  rrect13% 0.9x0.8 smd paste+0 mask+0: 1(-0.7,-0.55) 2(0.7,-0.55) 3(0.7,0.55) 4(-0.7,0.55)
FP-CX2016DB48000C0WPLA2_SMD4-MFG [mm]
  rrect13% 0.9x0.8 smd paste+0 mask+0: 1(-0.7,-0.55) 2(0.7,-0.55) 3(0.7,0.55) 4(-0.7,0.55)
  silkscreen extent -1.85,-1.35 1.05,1.35
FP-ERJ-1GNF4701C_0201-IPC_C [mil]
  rrect38% 13.94x10.34 smd paste+0 mask+0: 1(-10.01,0) 2(10.01,0)
FP-EXB-18VR000X_0502-MFG [mm]
  rrect57% 0.175x0.3 smd paste+0 mask+0: 1(-0.6,-0.275) 2(-0.2,-0.275) 3(0.2,-0.275) 4(0.6,-0.275) 5(0.6,0.275) 6(0.2,0.275) 7(-0.2,0.275) 8(-0.6,0.275)
"FP-GRM033R6YA104KE14D_0201 (0603 Metric)-IPC_C" [mil]
  rrect38% 13.94x10.34 smd paste+0 mask+0: 1(-10.01,0) 2(10.01,0)
"FP-GRM0335C1H8R0BA01D_0201 (0603 metric)-IPC_C" [mil]
  rrect38% 13.94x10.34 smd paste+0 mask+0: 1(-10.01,0) 2(10.01,0)
FP-GRPB052MWCN-RC_HDR10-MFG [mm]
  rrect9% 1.12x1.12 hole 0.7 paste-1000 mask+0: 1(-2.54,1.15)
  round 1.12 hole 0.7 paste-1000 mask+0: 2(-2.54,2.42) 3(-1.27,1.15) 4(-1.27,2.42) 5(0,1.15) 6(0,2.42) 7(1.27,1.15) 8(1.27,2.42) 9(2.54,1.15) 10(2.54,2.42)
  silkscreen extent -3.77,-0.7 3.42,1.17
FP-M50-3930342_HDR3-MFG [mm]
  rrect9% 1.1x1.1 hole 0.6 paste-1000 mask+0: 1(-1.27,1)
  round 1.1 hole 0.6 paste-1000 mask+0: 2(0,1) 3(1.27,1)
  silkscreen extent -2.15,-0.6 2.15,2.09
FP-M50-3930442_HDR4-RECOMMENDED_LAND_PATTERN [mm]
  rrect9% 1.1x1.1 hole 0.6 paste-1000 mask+0: 1(-1.905,1)
  round 1.1 hole 0.6 paste-1000 mask+0: 2(-0.635,1) 3(0.635,1) 4(1.905,1)
"FP-MCKK2012TR47M_0805 (2012 Metric)-IPC_C" [mil]
  rrect9% 45.45x53.39 smd paste+0 mask+0: 1(-26.61,0) 2(26.61,0)
"FP-RC0201JR-070RL_0201 (0603 Metric)-IPC_C" [mil]
  rrect38% 13.94x10.34 smd paste+0 mask+0: 1(-10.01,0) 2(10.01,0)
"FP-RC0201JR-070RL_0201 (0603 METRIC)-IPC_C" [mil]
  rrect38% 13.94x10.34 smd paste+0 mask+0: 1(-10.01,0) 2(10.01,0)
"FP-RC0201JR-070RL_0201 (0603 Metric)-MFG" [mm]
  rrect29% 0.35x0.4 smd paste+0 mask+0: 1(-0.325,0) 2(0.325,0)
"FP-RC0402FR-073R83L_0402 (1005 Metric)-IPC_C" [mil]
  rrect21% 20.29x18.6 smd paste+0 mask+0: 1(-14.9,0) 2(14.9,0)
FP-RR0306P-103-D_0201-IPC_C [mil]
  rrect37% 13.31x10.73 smd paste+0 mask+0: 1(-10.52,0) 2(10.52,0)
"FP-TMK063CG391JT-F_0201 (0603 Metric)-IPC_C" [mil]
  rrect38% 13.94x10.34 smd paste+0 mask+0: 1(-10.01,0) 2(10.01,0)
IND_LQG15H [mm] "MuRata"
  rect 0.55x0.6 smd: 1(-0.475,0) 2(0.475,0)
  silkscreen extent -1.3,-0.3 -0.95,0.3
MHNP_2-5 [mil]
  round 95 hole 100 unplated mask+0: ""(0,0)
  Keep-Out Layer circle w1: c0,0 r100
MHNP_M2_PANHEAD_PHILLIPS [mil]
  round 83 hole 88 unplated mask+0: ""(0,0)
  Keep-Out Layer circle w1: c0,0 r88
RGZ0048A [mm] "VQFN-48"
  rrect42% 0.6x0.24 smd: 1(-3.4,2.75) 2(-3.4,2.25) 3(-3.4,1.75) 4(-3.4,1.25) 5(-3.4,0.75) 6(-3.4,0.25) 7(-3.4,-0.25) 8(-3.4,-0.75) 9(-3.4,-1.25) 10(-3.4,-1.75) 11(-3.4,-2.25) 12(-3.4,-2.75) 25(3.4,-2.75) 26(3.4,-2.25) 27(3.4,-1.75) 28(3.4,-1.25) 29(3.4,-0.75) 30(3.4,-0.25) 31(3.4,0.25) 32(3.4,0.75) 33(3.4,1.25) 34(3.4,1.75) 35(3.4,2.25) 36(3.4,2.75)
  rrect42% 0.24x0.6 smd: 13(-2.75,-3.4) 14(-2.25,-3.4) 15(-1.75,-3.4) 16(-1.25,-3.4) 17(-0.75,-3.4) 18(-0.25,-3.4) 19(0.25,-3.4) 20(0.75,-3.4) 21(1.25,-3.4) 22(1.75,-3.4) 23(2.25,-3.4) 24(2.75,-3.4) 37(2.75,3.4) 38(2.25,3.4) 39(1.75,3.4) 40(1.25,3.4) 41(0.75,3.4) 42(0.25,3.4) 43(-0.25,3.4) 44(-0.75,3.4) 45(-1.25,3.4) 46(-1.75,3.4) 47(-2.25,3.4) 48(-2.75,3.4)
  rrect2% 5.15x5.15 smd paste-2.6: 49(0,0)
RNF0026C [mm] "QFN, 26-Leads, Body 4x4.5mm, Pitch 0.5mm"
  rrect25% 0.6x0.4 smd paste-0.3: 1(-1.9,1.825) 8(-1.9,-1.825) 14(1.9,-1.825) 21(1.9,1.825)
  rrect40% 0.6x0.25 smd paste+0: 2(-1.9,1.25) 3(-1.9,0.75) 4(-1.9,0.25) 5(-1.9,-0.25) 6(-1.9,-0.75) 7(-1.9,-1.25) 15(1.9,-1.25) 16(1.9,-0.75) 17(1.9,-0.25) 18(1.9,0.25) 19(1.9,0.75) 20(1.9,1.25)
  rrect40% 0.25x1.82 smd paste-1: 9(-1,-1.54) 10(-0.5,-1.54) 11(0,-1.54) 12(0.5,-1.54) 13(1,-1.54) 22(1,1.54) 23(0.5,1.54) 24(0,1.54) 25(-0.5,1.54) 26(-1,1.54)
  rrect15% 2.24x0.66 smd paste-1: 27(0,0)
  rrect33% 0.6x0.3 on Top Paste: ""(-1.9,1.775) ""(-1.9,-1.775) ""(1.9,1.775) ""(1.9,-1.775)
  rrect33% 0.3x0.825 on Top Paste: ""(-1.575,2.037) ""(-1.575,-2.037) ""(1.575,2.037) ""(1.575,-2.037)
  rrect40% 0.25x0.81 on Top Paste: ""(-1,1.035) ""(-1,2.045) ""(-1,-2.045) ""(-1,-1.035) ""(-0.5,2.045) ""(-0.5,1.035) ""(-0.5,-1.035) ""(-0.5,-2.045) ""(0,2.045) ""(0,1.035) ""(0,-1.035) ""(0,-2.045) ""(0.5,2.045) ""(0.5,1.035) ""(0.5,-1.035) ""(0.5,-2.045) ""(1,1.035) ""(1,2.045) ""(1,-2.045) ""(1,-1.035)
  rrect15% 0.98x0.66 on Top Paste: ""(-0.59,0) ""(0.59,0)
  silkscreen extent -2.45,-2.7 2.45,2.7
RSE0010A [mm] "QFN, 10-Leads, Body 1.5x2mm, Pitch 0.5mm, TI Recommended"
  rect 0.55x0.2 smd: 1(-0.675,0.75) 2(-0.675,0.25) 3(-0.675,-0.25) 4(-0.675,-0.75) 6(0.675,-0.75) 7(0.675,-0.25) 8(0.675,0.25) 9(0.675,0.75)
  rect 0.3x0.6 smd: 5(0,-0.9) 10(0,0.9)
  silkscreen extent -1.07,-1.17 0.77,1.18
RSV0016A [mm] "QFN, 16-Leads, Body 1.8x2.6mm, Pitch 0.4mm, TI Recommended"
  rect 0.7x0.2 smd: 1(-0.75,0.6)
  rect 0.6x0.2 smd: 2(-0.8,0.2) 3(-0.8,-0.2) 4(-0.8,-0.6) 9(0.8,-0.6) 10(0.8,-0.2) 11(0.8,0.2) 12(0.8,0.6)
  rect 0.2x0.6 smd: 5(-0.6,-1.2) 6(-0.2,-1.2) 7(0.2,-1.2) 8(0.6,-1.2) 13(0.6,1.2) 14(0.2,1.2) 15(-0.2,1.2) 16(-0.6,1.2)
  silkscreen extent -1.08,-1.33 1.08,1.45
RUT0012A [mm] "QFN, 12-Leads, Body 1.7x2mm, Pitch 0.4mm, TI Recommended"
  rrect50% 0.7x0.2 smd: 1(-0.7,0.8) 2(-0.7,0.4) 3(-0.7,0) 4(-0.7,-0.4) 5(-0.7,-0.8) 7(0.7,-0.8) 8(0.7,-0.4) 9(0.7,0) 10(0.7,0.4) 11(0.7,0.8)
  rrect50% 0.2x0.7 smd: 6(0,-0.85) 12(0,0.85)
  silkscreen extent -0.9,-1.2 0.9,1.2
Samtec_QSH-030-01-X-D-A [mm] "Receptacle, 0.5 mm, 30x2, TH"
  rect 2.27x0.279 smd: 1(-2.865,7.25) 2(2.865,7.25) 3(-2.865,6.75) 4(2.865,6.75) 5(-2.865,6.25) 6(2.865,6.25) 7(-2.865,5.75) 8(2.865,5.75) 9(-2.865,5.25) 10(2.865,5.25) 11(-2.865,4.75) 12(2.865,4.75) 13(-2.865,4.25) 14(2.865,4.25) 15(-2.865,3.75) 16(2.865,3.75) 17(-2.865,3.25) 18(2.865,3.25) 19(-2.865,2.75) 20(2.865,2.75) 21(-2.865,2.25) 22(2.865,2.25) 23(-2.865,1.75) 24(2.865,1.75) 25(-2.865,1.25) 26(2.865,1.25) 27(-2.865,0.75) 28(2.865,0.75) 29(-2.865,0.25) 30(2.865,0.25) 31(-2.865,-0.25) 32(2.865,-0.25) 33(-2.865,-0.75) 34(2.865,-0.75) 35(-2.865,-1.25) 36(2.865,-1.25) 37(-2.865,-1.75) 38(2.865,-1.75) 39(-2.865,-2.25) 40(2.865,-2.25) 41(-2.865,-2.75) 42(2.865,-2.75) 43(-2.865,-3.25) 44(2.865,-3.25) 45(-2.865,-3.75) 46(2.865,-3.75) 47(-2.865,-4.25) 48(2.865,-4.25) 49(-2.865,-4.75) 50(2.865,-4.75) 51(-2.865,-5.25) 52(2.865,-5.25) 53(-2.865,-5.75) 54(2.865,-5.75) 55(-2.865,-6.25) 56(2.865,-6.25) 57(-2.865,-6.75) 58(2.865,-6.75) 59(-2.865,-7.25) 60(2.865,-7.25)
  round 0 hole 1.02 unplated: MH1(2.67,10.065) MH2(2.67,-10.065)
  rect 0.43x2.54 smd: MP1(0,8.065) MP4(0,-8.065)
  rect 0.43x4.7 smd: MP2(0,3.175) MP3(0,-3.175)
  silkscreen extent -3.9,-10.66 3.62,10.66
SW_218-4LPST [mil] "CTS Components"
  rect 50x30 smd: 1(-150,75) 2(-150,25) 3(-150,-25) 4(-150,-75) 5(150,-75) 6(150,-25) 7(150,25) 8(150,75)
  silkscreen extent -114,-123 114,123
SW_B3U-1000P [mm] "OMRON"
  rect 0.8x1.7 smd: 1(-1.7,0) 2(1.7,0)
  silkscreen extent -1.5,-1.25 1.5,1.25
TP_25MIL-SMT [mil]
  round 25 smd mask+0: 1(0,0)
TP_VIA_060RND040 [mil] "TP_VIA_060RND040"
  round 60 hole 40: 1(0,0)
USON-8L [mm] "SON, 8-Leads, Body 3x2mm, Pitch 0.5mm"
  rrect40% 0.6x0.25 smd: 1(-1.4,0.75) 2(-1.4,0.25) 3(-1.4,-0.25) 4(-1.4,-0.75) 5(1.4,-0.75) 6(1.4,-0.25) 7(1.4,0.25) 8(1.4,0.75)
  rrect50% 0.2x1.6 smd: 9(0,0)
  silkscreen extent -1.55,-1.17 0.65,1.17

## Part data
A1: library part CMP-0087189-1, "RF ANT 2.4GHZ CHIP SOLDER SMD"
C1 C4 C7 C42 C50 C51 C52 C53 C55 C59 C62 C65 C70 C73 C78 C82 C122: library part CMP-0006339-4, "CAP, CERM, 10 uF, 10 V, +/- 20%, X5R, 0402"
C2 C3 C6 C9 C10 C12 C13 C25 C26 C27 C35 C36 C37 C40 C43 C72 C86 C91 C92 C101 C105 C107 C108 C109 C114 C117 C118 C119 C120 C123 C126 C127 C128 C130: library part CMP-0086440-1, "Cap Ceramic 0.1uF 35V X5R 10% Pad SMD 0201 85C T/R"
C5 C11 C15 C16 C24 C100 C115 C116 C129: library part CMP-0086446-1, "1µF ±20% 16V Ceramic Capacitor X5R 0201"
C8 C125: library part CMP-0086445-1, "CAP CER 10000PF 25V X5R 0201"
C14 C71: library part CMP-0080076-1, "CAP, CERM, 4.7 pF, 50 V,+/- 3%, C0G/NP0, 0201"
C17 C18: library part CMP-0086441-1, "Cap Ceramic 8pF 50V C0G 0.1pF SMD 0201 125°C Paper T/R"
C19 C20 C38 C39: library part CMP-0087190-1, "CAP CER 12PF 25V C0G/NP0 0201"
C21 C93: library part CMP-0006345-2, "CAP, CERM, 12 pF, 50 V, +/- 5%, C0G/NP0, 0402"
C22 C23 C41: library part CMP-0085178-1, "CAP, CERM, 1 pF, 50 V,+/- 25%, C0G/NP0, AEC-Q200 Grade 1, 0402"
C28 C29 C44 C45 C46 C47 C48 C49 C54 C77: library part CMP-0089043-3, "CAP CER 22UF 6.3V X5R 0402"
C30 C56 C57 C58 C60 C61 C63 C64 C66 C67 C68 C75 C76 C80 C81 C84 C85 C87 C88 C94 C95 C96 C97 C98: library part CMP-0009781-1, "CAP, CERM, 0.22 uF, 10 V, +/- 20%, X5R, 0201"
C31 C32 C33 C34: library part CMP-0086438-1, "CAP CER 390PF 25V C0G/NP0 0201"
C69: library part CMP-0009718-2, "CAP, CERM, 0.047 uF, 16 V, +/- 10%, X5R, 0201"
C74 C79 C83 C102 C103: library part CMP-0009657-3, "CAP, CERM, 2.2 uF, 6.3 V, +/- 20%, X5R, 0201"
C89 C90: library part CMP-0081763-1, "CAP, CERM, 1 µF, 6.3 V,+/- 10%, X6S, 0402"
C99 C104: library part CMP-0086306-1, "CAP, CERM, 1.8 pF, 50 V,+/- 6%, C0G/NP0, 0402"
C106 C110: library part CMP-0006692-2, "CAP, CERM, 4700 pF, 50 V, +/- 10%, X7R, 0402"
D1 D2: library part CMP-0028829-2, "Diode, Schottky, 30 V, 2 A, 2-XFDFN"
FID1 FID2 FID3 FID4 FID5 FID6: library part CMP-0077181-1, "Fiducial mark.  There is nothing to buy or mount."
FL1 FL2 FL3 FL6 FL7 FL8 FL9 FL10 FL11 FL12 FL14 FL20 FL22: library part CMP-0078934-1, "Inductor, Ferrite Bead, Ferrite, 2.2 A, 0.035 ohm, AEC-Q200 Grade 1, SMD"
J1 J5: library part CMP-0055293-1, "Connector, Receptacle, Micro-USB Type B, R/A, Bottom Mount SMT"
J2: library part CMP-0075524-1, "Receptacle, 0.5 mm, 30x2, Gold, TH"
J3: library part CMP-0087187-1, "CONN HDR 1.27MM R/A AU 4POS"
J4 J6: library part CMP-0086453-1, "Easy-On™ Type FFC/FPC Connector, Right-Angle, Surface Mount, ZIF, Bottom Contact Style, 1.10mm Mated Height, 10 Circuits"
J7: library part CMP-0087786-1, "CONN HEADER R/A 10POS 1.27MM"
J8 J10: library part CMP-0087785-1, "CONN HEADER R/A 3POS 1.27MM"
J9: library part CMP-0075320-1, "Receptacle, Ultra Miniature Coaxial, Male Pin, 50 ohm, SMT"
L1 L6: library part CMP-0058626-1, "Inductor, Multilayer, Air Core, 2.4 nH, 0.3 A, 0.15 ohm, SMD"
L2 L3 L4 L5: library part CMP-0087178-1, "FIXED IND 470NH 4.5A 39 MOHM SMD"
L7: library part CMP-0062727-1, "Inductor, Multilayer, Ferrite, 6.8 uH, 0.11 A, 0.25 ohm, SMD"
L8: library part CMP-0003349-2, "Ferrite Bead, 1500 ohm @ 100 MHz, 0.5 A, 0603"
L9 L10: library part CMP-0058624-1, "Inductor, Multilayer, Air Core, 2 nH, 0.3 A, 0.1 ohm, SMD"
L11 L12 L13 L14: library part CMP-0003354-2, "Ferrite Bead, 26 ohm @ 100 MHz, 6 A, 0603"
LD1 LD2 LD3 LD4 LD5 LD6: library part CMP-0067682-2, "LED, Green, SMD"
Q1: library part CMP-0087176-1, "MOSFET N-CH 100V 170MA SOT23-3"
R1 R3 R7 R8 R18 R19 R20 R21 R22 R23 R35 R36 R43 R44 R45 R59 R65 R77 R78 R80 R81 R82 R83 R84 R85 R93 R94 R95 R96 R98 R104 R110 R118 R122 R124 R125 R134 R177 R178: library part CMP-0088002-1, "10 kOhms ±0.5% 0.05W, 1/20W Chip Resistor 0201 (0603 Metric)  Thin Film"
R2 R12 R14 R28 R30 R31 R32 R41 R51 R57 R58 R60 R61 R62 R63 R66 R67 R68 R70 R71 R72 R73 R74 R76 R86 R87 R90 R91 R97 R99 R100 R101 R102 R103 R105 R106 R109 R112 R113 R115 R116 R120 R121 R123 R127 R128 R129 R131 R136 R139 R160 R161 R166 R168 R182 R183 R184 R185: library part CMP-0086442-2, "RES SMD 0 OHM JUMPER 1/20W 0201"
R4 R5 R9 R29 R37 R89 R92: library part CMP-0027261-3, "RES, 100 k, 1%, 0.05 W, 0201"
R6 R46 R47 R48 R49: library part CMP-0027275-3, "RES, 33.2, 1%, 0.05 W, 0201"
R10 R11 R88 R130 R132 R133 R135 R137 R138 R140: library part CMP-0087185-1, "RES SMD 20 OHM 1% 1/20W 0201"
R13 R15 R17 R42 R111: library part CMP-0027072-1, "RES, 220, 5%, 0.05 W, 0201"
R16 R174 R176: library part CMP-0027880-1, "RES, 7.87 k, 1%, 0.05 W, 0201"
R24: library part CMP-0087183-1, "RES SMD 200 OHM 1% 1/5W 0402"
R25 R26 R33 R34 R38 R40 R64 R69 R141: library part CMP-0027745-1, "RES, 4.99 k, 1%, 0.05 W, 0201"
R27 R39 R107 R108: library part CMP-0027137-1, "RES, 510, 5%, 0.05 W, 0201"
R50 R75: library part CMP-0027052-1, "RES, 1.0 k, 5%, 0.05 W, 0201"
R52: library part CMP-0027452-1, "RES, 1.96 k, 1%, 0.05 W, 0201"
R53 R54 R55 R56: library part CMP-0086444-2, "RES Thick Film SMD 3.83O 1% 1/16W 0402 200ppm/°C"
R79 R180 R181: library part CMP-0087184-1, "RESISTOR, 0201, 0.05W, 1%, 4K7"
R114 R117 R119 R126: library part CMP-0026491-2, "RES, 61.9, 1%, 0.063 W, AEC-Q200 Grade 0, 0402"
R158 R170 R172: library part CMP-0027891-1, "RES, 82.5 k, 1%, 0.05 W, 0201"
R159 R171: library part CMP-0027165-1, "RES, 750, 5%, 0.05 W, 0201"
RA1 RA2 RA3 RA4 RA5 RA6 RA7 RA8 RA9: library part CMP-0087186-1, "RES ARRAY 4 RES ZERO OHM 0502"
S1 S2: library part CMP-0002128-2, "Switch, Slide, SPST 4 poles, SMT"
S3: library part CMP-0087181-1, "SWITCH SLIDE DIP SPST 100MA 6V"
SW2 SW3: library part CMP-0002150-2, "SWITCH TACTILE SPST-NO 0.05A 12V"
TP2 TP3 TP4 TP5 TP6 TP7 TP8 TP9 TP10 TP11 TP12 TP13 TP14 TP15 TP16 TP17 TP18 TP19 TP26 TP27 TP46: library part CMP-0078143-3, "TEST POINT.  No entry in BOM."
TP20: library part CMP-0086474-1, "PC Test Point, Loop Brass, Tin Plating 0.047\" (1.19mm) Hole Diameter Mounting Type"
U1: library part CMP-0079120-2, "4-A + 2.5-A + Two 1.5-A Buck Converters With Integrated Switches, RNF0026C (VQFN-HR-26)"
U2: library part CMP-0860942-2, "XI6843ARQGALP, ALP0180A (BGA-180)"
U3: library part CMP-0087172-1, "I/O Controller Interface IC USB to Dual UART bridge"
U4: library part CMP-0035419-1, "Single Output High PSRR LDO, 200 mA, Fixed 3 V Output, 2.7 to 5.5 V Input, 5-pin SOT-23 (DBV), -40 to 85 degC, Green (RoHS & no Sb/Br)"
U5: library part CMP-0067398-2, "Automotive Grade, 1.4V-Capable +/-0.5degC Temperature Sensor with Alert Function and I2C/SMBus, DRL0006A (SOT-OTHER-6)"
U6: library part CMP-0087170-1, "8KB I2C SER EEPROM TSOT 23"
U7: library part CMP-0087171-1, "IMU ACCEL/GYRO/MAG I2C 32BIT"
U8: library part CMP-0083675-2, "SimpleLink(TM) Bluetooth(R) 5 low energy Wireless MCU, RGZ0048A (VQFN-48)"
U9: library part CMP-0078466-1, "ULTRA LOW POWER, 16M-BIT [x 1/x 2/x 4] CMOS MXSMIO (SERIAL MULTI I/O) FLASH MEMORY, SON-8"
U10: library part CMP-0043349-1, "Low-Voltage 8-Bit I2C and SMBus I/O Expander, 1.65 to 5.5 V, -40 to 85 degC, 16-pin UQFN (RSV), Green (RoHS & no Sb/Br)"
U11: library part CMP-0050992-5, "1-Channel, 2:1 Analog Switch, DSF0006A (X2SON-6)"
U12 U17: library part CMP-0065183-3, "Automotive Fault Protected CAN Transceiver With Flexible Data-Rate, DRB0008F (VSON-8)"
U13: library part CMP-0067415-1, "10-Ohm Quad SPDT Analog Switch, RSV0016A (UQFN-16)"
U14: library part CMP-0860038-1, "Automotive 4-Bit Bidirectional Voltage-Level Translator with Auto Direction Sensing and +/-15kV ESD, RUT0012A (UQFN-12)"
U15 U18: library part CMP-0074545-1, "Dual 10-ohm SPDT Analog Switch, RSE0010A (UQFN-10)"
U16: library part CMP-0087998-2, "AND Gate IC 1 Channel  6-SON (1x1)"
U19: library part CMP-0043358-3, "Dual In / Single Out Autoswitching Power Mux, 2.8 to 5.5 V, -40 to 85 degC, 8-pin SON (DRB), Green (RoHS & no Sb/Br)"
Y1: library part CMP-0087164-1, "CRYSTAL 40.0000MHZ 8PF SMD"
Y2: library part CMP-0088076-1, "48MHz ±20ppm Crystal 7pF 50 Ohms 4-SMD, No Lead"
Y3 Y4: library part CMP-0088006-1, "CRYSTAL 32.768KHZ 4PF SMD"
ZZ1: library part CMP-0003616-3
ZZ2: library part CMP-0077236-1
ZZ3: library part CMP-0077237-1
ZZ4 ZZ5.2: library part CMP-0077238-1
ZZ5.1: library part CMP-0077238-1, "Cut the thermal pad(Part Number#GPVOUS-0.125-AC-0816) for the shape and size of the inner surface of the heatsink(Part Number#160018120021) and paste it on the inner surface of the heatsink;"

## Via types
v1: diameter 18, hole 8, Top Layer to Bottom Layer, tented both sides, 737 vias
v2: diameter 19.68, hole 7.87, Top Layer to Bottom Layer, tented both sides, 36 vias
v3: diameter 17, hole 8, Top Layer to Bottom Layer, tented both sides, 1 vias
